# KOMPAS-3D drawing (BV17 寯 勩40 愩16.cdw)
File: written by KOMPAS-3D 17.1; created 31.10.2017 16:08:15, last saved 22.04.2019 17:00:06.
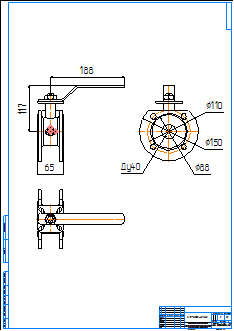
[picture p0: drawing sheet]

Sheet 1: A1, portrait

Title block, sheet 1: name: BV17 МФ Ду40 Ру16; material: Внимание! Данный продукт является объектом авторского права ООО «Торговый Дом АДЛ». / Запрещается изменение, копирование, распространение / (в том числе путем копирования на другие сайты и ресурсы в Интернете) / или любое иное использование информации и объектов без предварительного / согласия правообладателя (ООО «Торговый Дом АДЛ»).; mass: 1; sheets: 1; organisation: ООО "Торговый дом АДЛ"; sheet format: A1; stored path: \\adlc.lan\data\АДЛ_ПКД\3D-модели\ADL production\Краны шаровые серии BV\BV17 МФ Нержавеющие Ру16\KOMPAS 2D\BV17 МФ Ду40 Ру16.cdw

Views: Вид 1, Проекционный вид 2, Проекционный вид 3
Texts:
  kka
  adl
Dimensions and other numbers on the sheet: 65; 188; 117; 40; 150; 110; 88; 1:1; 1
